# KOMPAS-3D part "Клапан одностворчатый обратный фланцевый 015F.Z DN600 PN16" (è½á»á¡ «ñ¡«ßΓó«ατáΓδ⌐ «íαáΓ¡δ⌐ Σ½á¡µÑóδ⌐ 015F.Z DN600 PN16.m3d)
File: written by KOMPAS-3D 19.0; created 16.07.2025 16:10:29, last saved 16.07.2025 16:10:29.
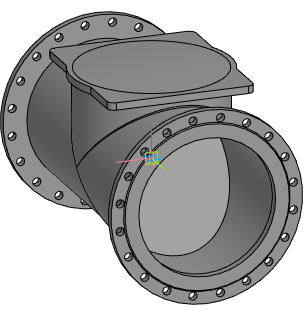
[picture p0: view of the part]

Document properties: Полное имя файла: E:\Dendor Работа Сачек\3D для проектировщиков\5.4 Тип 015F.Z. Клапан одностворчатый обратный фланцевый\stp_Клапан одностворчатый обратный фланцевый 015F.Z PN10_16\Клапан одностворчатый обратный фланцевый 015F.Z DN600 PN16.m3d

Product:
- Part/product: Клапан одностворчатый обратный фланцевый 015F.Z DN600 PN16

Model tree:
1. Операция без истории:1  (labels: Клапан одностворчатый обратный фланцевый 015F.Z DN600 PN16)
2. Операция без истории:2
